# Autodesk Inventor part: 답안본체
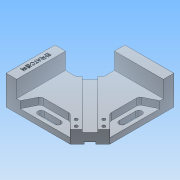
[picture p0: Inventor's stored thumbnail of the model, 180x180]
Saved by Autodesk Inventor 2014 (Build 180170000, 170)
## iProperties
Created: 2019-04
Part Number: 답안본체
Material: 알루미늄 6061
Document SubType Name: Modeling
Designer: net
Density: 2.71 g/cm^3
Appearance: 알루미늄 - 평지
Mass: 603.738 g
Surface Area: 426.536 cm^2
Volume: 222.782 cm^3
Author: net
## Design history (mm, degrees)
sketch "스케치1"
  geometry: L1 (-60, -60)-(60, -60); L2 (60, -60)-(60, 60); L3 (60, 60)-(-60, 60); L4 (-60, 60)-(-60, -60); L5 (-60, -60)-(60, 60); L6 (60, -60)-(-60, 60); 1 further point
  constraints: 12 end point, 2 midpoint, 2 parallel, 1 horizontal, 1 perpendicular
  dimensions: "d0" = 120 distance of L2.end L3.end; "d1" = 120 distance of L3.end L1.start
extrude "돌출1" new body sketch "스케치1" stored distance "d2" = 42; taper "d3" = 0 deg
sketch "스케치2"
  geometry: L1 (-60, -60)-(60, -60) reference; L2 (60, -60)-(60, 60) reference; L3 (31.716, -60)-(60, -31.716); 1 further point
  constraints: 2 end point, 2 point on line
  dimensions: "d7" = 20 distance from line of L1.end L3
extrude "돌출2" cut sketch "스케치2" distance "d8" = 42; taper "d9" = 0 deg
sketch "스케치3"
  geometry: L1 (31.716, -60)-(60, -31.716) reference; L2 (60, 60)-(-60, 60) reference; L3 (-60, 60)-(-60, -60) reference; L4 (-60, 10)-(-10, 10); L5 (-10, 10)-(-10, 60); L6 (-10, 29.806)-(-29.806, 10); 1 further point
  constraints: 6 end point, 4 point on line, 2 perpendicular, 1 parallel
  dimensions: "d10" = 50 distance of L4.end L5.end; "d11" = 50 distance of L4.start L4.end; "d12" = 93 distance between parallel lines of L1 L6
extrude "돌출3" cut sketch "스케치3" distance "d13" = 42; taper "d14" = 0 deg
sketch "스케치4"
  geometry: L1 (-10, 60)-(-10, 29.806) reference; L2 (-10, 29.806)-(-29.806, 10) reference; L3 (-29.806, 10)-(-60, 10) reference; L4 (-60, 10)-(-60, -60) reference; L5 (-60, -60)-(31.716, -60) reference; L6 (31.716, -60)-(60, -31.716) reference; L7 (60, -31.716)-(60, 60) reference; L8 (60, 60)-(-10, 60) reference; L9 (-45, 10)-(-45, -60); L10 (-10, 45)-(60, 45); 1 further point
  constraints: 4 end point, 4 point on line, 2 perpendicular
  dimensions: "d15" = 15 distance between parallel lines of L4 L9; "d16" = 15 distance between parallel lines of L8 L10
extrude "돌출4" cut sketch "스케치4" distance "d17" = 24; taper "d18" = 0 deg
sketch "스케치5"
  geometry: L1 (-29.806, 10)-(-10, 29.806) reference; L2 (31.716, -60)-(-45, -60) reference; L3 (60, -31.716)-(31.716, -60) reference; L4 (-10, 29.806)-(-10, 45) reference; L5 (-40, -60)-(-30, -40); L6 (-30, -40)-(11.716, -40); L7 (11.716, -40)-(31.716, -60); L8 (-60, 10)-(-60, -60) reference; L9 (-19.903, 19.903)-(45.858, -45.858); 1 further point
  constraints: 8 end point, 2 midpoint, 2 point on line, 1 parallel, 1 perpendicular
  dimensions: "d19" = 20 distance from line of L5.start L8; "d20" = 30 horizontal distance of L8.end L5.end; "d21" = 20 distance between parallel lines of L9 L7; "d22" = 20 distance between parallel lines of L2 L6
extrude "돌출5" cut sketch "스케치5" distance "d23" = 10; taper "d24" = 0 deg
sketch "스케치6"
  geometry: L1 (60, -31.716)-(31.716, -60) reference; L2 (60, 45)-(60, -31.716) reference; L3 (-29.806, 10)-(-10, 29.806) reference; L4 (-30, -40)-(11.716, -40) reference; L5 (60, 40)-(40, 30); L6 (40, 30)-(40, -11.716); L7 (40, -11.716)-(60, -31.716); L8 (-19.903, 19.903)-(45.858, -45.858); L9 (60, 60)-(-10, 60) reference; 1 further point
  constraints: 8 end point, 2 midpoint, 2 perpendicular, 1 parallel, 1 point on line
  dimensions: "d25" = 20 distance from line of L9 L5.start; "d26" = 30 distance from line of L9 L5.end; "d27" = 20 distance between parallel lines of L2 L6
extrude "돌출6" cut sketch "스케치6" distance "d28" = 10; taper "d29" = 0 deg
fillet "모깎기1" dims "d30" = 5
sketch "스케치7"
  geometry: L1 (-26.91, -40)-(9.645, -40) reference; L2 (31.716, -60)-(-40, -60) reference; L3 (-20, -50)-(4, -50); L4 (-20, -54.5)-(4, -54.5); L5 (4, -45.5)-(-20, -45.5); L6 (-60, 10)-(-60, -60) reference; A1 r 4.5 centre (-20, -50) between (-20, -45.5) and (-20, -54.5); A2 r 4.5 centre (4, -50) between (4, -54.5) and (4, -45.5); 2 further points
  constraints: 8 end point, 4 point on circle, 4 tangent, 2 centre point, 2 parallel, 1 midpoint
  dimensions: "d31" = 10 distance from line of L2 point (-8, -50); "d32" = 9 distance between parallel lines of L4 L5; "d33" = 40 distance from line of L6 L3.start; "d34" = 24 distance of L4.start L4.end
extrude "돌출7" cut sketch "스케치7" distance "d35" = 10; taper "d36" = 0 deg
sketch "스케치8"
  geometry: L1 (60, 40)-(60, -31.716) reference; L2 (40, -9.645)-(40, 26.91) reference; L3 (50, 20)-(50, -4); L4 (45.5, 20)-(45.5, -4); L5 (54.5, -4)-(54.5, 20); L6 (60, 60)-(-10, 60) reference; A1 r 4.5 centre (50, 20) between (54.5, 20) and (45.5, 20); A2 r 4.5 centre (50, -4) between (45.5, -4) and (54.5, -4); 2 further points
  constraints: 8 end point, 4 point on circle, 4 tangent, 2 centre point, 2 parallel, 1 midpoint
  dimensions: "d37" = 9 distance between parallel lines of L5 L4; "d38" = 10 distance from line of L1 point (50, 8); "d39" = 24 distance of L4.start L4.end; "d40" = 40 distance from line of L6 L3.start
extrude "돌출8" cut sketch "스케치8" distance "d41" = 10; taper "d42" = 0 deg
sketch "스케치9"
  geometry: L1 (-40, 0)-(0, 0) reference; L2 (-40, 18)-(0, 18) reference; L3 (-14, 15)-(-26, 15); L4 (-26, 15)-(-26, 18); L5 (-26, 18)-(-14, 18); L6 (-14, 18)-(-14, 15); L7 (-14, 15)-(-26, 18); L8 (-26, 15)-(-14, 18); L9 (-12, 3.5)-(-28, 3.5); L10 (-28, 3.5)-(-28, 0); L11 (-28, 0)-(-12, 0); L12 (-12, 0)-(-12, 3.5); L13 (-12, 3.5)-(-28, 0); L14 (-28, 3.5)-(-12, 0); 5 further points
  constraints: 24 end point, 6 midpoint, 4 parallel, 2 horizontal, 2 perpendicular, 2 point on line, 2 vertical alignment
  dimensions: "d43" = 16 distance of L9.start L9.end; "d44" = 3.5 distance of L11.end L9.start; "d45" = 12 distance of L3.start L3.end; "d46" = 3 distance of L3.end L4.end
extrude "돌출9" cut sketch "스케치9" stored distance "d47" = 10; taper "d48" = 0 deg
sketch "스케치10"
  geometry: L1 (40.201, -51.515)-(-25.56, 14.246) reference; L2 (40.201, -51.515)-(31.716, -60) reference; L3 (9.645, -40)-(-26.91, -40) reference; L4 (-31.382, -42.764)-(-40, -60) reference; L5 (-40, -60)-(-45, -60) reference; L6 (-45, -60)-(-60, -60) reference; L7 (-60, -60)-(-60, 10) reference; L8 (-60, 10)-(-45, 10) reference; L9 (-45, 10)-(-29.806, 10) reference; L10 (-29.806, 10)-(-25.56, 14.246) reference; L11 (-25.56, 14.246)-(40.201, -51.515) reference; L12 (40.201, -51.515)-(31.716, -60) reference; L13 (31.716, -60)-(13.18, -41.464) reference; L14 (-45, 10)-(-45, -60) reference; L15 (60, 45)-(-10, 45) reference; L16 (-10, 29.806)-(-10, 45) reference; L17 (-14.246, 25.56)-(-10, 29.806) reference; L18 (51.515, -40.201)-(-14.246, 25.56) reference; L19 (60, -31.716)-(51.515, -40.201) reference; L20 (41.464, -13.18)-(60, -31.716) reference; L21 (40, 26.91)-(40, -9.645) reference; L22 (60, 40)-(42.764, 31.382) reference; L23 (60, 45)-(60, 40) reference; L24 (60, 60)-(60, 45) reference; L25 (-10, 60)-(60, 60) reference; L26 (-10, 45)-(-10, 60) reference; L27 (9.645, -40)-(-26.91, -40) reference; L28 (-31.382, -42.764)-(-40, -60) reference; L29 (-40, -60)-(-45, -60) reference; L30 (-45, -60)-(-60, -60) reference; L31 (-60, -60)-(-60, 10) reference; L32 (-60, 10)-(-45, 10) reference; L33 (-45, 10)-(-29.806, 10) reference; L34 (-29.806, 10)-(-25.56, 14.246) reference; L35 (-25.56, 14.246)-(40.201, -51.515) reference; L36 (40.201, -51.515)-(31.716, -60) reference; L37 (31.716, -60)-(13.18, -41.464) reference; L38 (-45, 10)-(-45, -60) reference; L39 (60, 45)-(-10, 45) reference; L40 (-10, 29.806)-(-10, 45) reference; L41 (-14.246, 25.56)-(-10, 29.806) reference; L42 (51.515, -40.201)-(-14.246, 25.56) reference; L43 (60, -31.716)-(51.515, -40.201) reference; L44 (41.464, -13.18)-(60, -31.716) reference; L45 (40, 26.91)-(40, -9.645) reference; L46 (60, 40)-(42.764, 31.382) reference; L47 (60, 45)-(60, 40) reference; L48 (60, 60)-(60, 45) reference; L49 (-10, 60)-(60, 60) reference; L50 (-10, 45)-(-10, 60) reference; C1 r 2.25 at (31.716, -51.515); C2 r 2.25 at (23.23, -43.029); C3 r 2.25 at (43.029, -23.23); C4 r 2.25 at (51.515, -31.716); A1 r 5 centre (9.645, -45) between (13.18, -41.464) and (9.645, -40) reference; A2 r 5 centre (-26.91, -45) between (-26.91, -40) and (-31.382, -42.764) reference; A3 r 5 centre (45, -9.645) between (40, -9.645) and (41.464, -13.18) reference; A4 r 5 centre (45, 26.91) between (42.764, 31.382) and (40, 26.91) reference; A5 r 5 centre (9.645, -45) between (13.18, -41.464) and (9.645, -40) reference; A6 r 5 centre (-26.91, -45) between (-26.91, -40) and (-31.382, -42.764) reference; A7 r 5 centre (45, -9.645) between (40, -9.645) and (41.464, -13.18) reference; A8 r 5 centre (45, 26.91) between (42.764, 31.382) and (40, 26.91) reference; 1 further point
  constraints: 4 centre point
  dimensions: "d49" = 4.5 diameter of C1; "d50" = 4.5 diameter of C2; "d51" = 4.5 diameter of C3; "d52" = 4.5 diameter of C4; "d53" = 6 distance from line of L2 C1.centre; "d54" = 6 distance from line of L1 C1.centre; "d55" = 6 distance from line of L43 C4.centre; "d56" = 6 distance from line of L42 C4.centre; "d57" = 18 distance from line of L2 C2.centre; "d58" = 18 distance from line of L19 C3.centre; "d59" = 6 distance from line of L20 C3.centre; "d60" = 6 distance from line of L1 C2.centre
extrude "돌출10" cut sketch "스케치10" stored distance "d61" = 10; taper "d62" = 0 deg
sketch "스케치11"
  geometry: L1 (15.66, 24.146)-(-50.101, -41.615) reference; L2 (-50.101, -41.615)-(-60, -31.716) reference; L3 (-60, -31.716)-(-60, 60) reference; L4 (-60, 60)-(10, 60) reference; L5 (10, 60)-(10, 29.806) reference; L6 (10, 29.806)-(15.66, 24.146) reference; L7 (-54.5, 20)-(-54.5, -4) reference; L8 (-45.5, -4)-(-45.5, 20) reference; L9 (20, -45.5)-(-4, -45.5) reference; L10 (-4, -54.5)-(20, -54.5) reference; L11 (60, -60)-(-31.716, -60) reference; L12 (-31.716, -60)-(-41.615, -50.101) reference; L13 (-41.615, -50.101)-(24.146, 15.66) reference; L14 (24.146, 15.66)-(29.806, 10) reference; L15 (29.806, 10)-(60, 10) reference; L16 (60, 10)-(60, -60) reference; C1 r 2.25 at (-31.716, -51.515) reference; C2 r 2.25 at (-23.23, -43.029) reference; C3 r 2.25 at (-31.716, -51.515) reference; C4 r 2.25 at (-43.029, -23.23) reference; C5 r 2.25 at (-51.515, -31.716) reference; C6 r 2.25 at (-23.23, -43.029) reference; C7 r 4 at (-43.029, -23.23); C8 r 4 at (-51.515, -31.716); C9 r 4 at (-23.23, -43.029); C10 r 4 at (-31.716, -51.515); A1 r 4.5 centre (-50, 20) between (-45.5, 20) and (-54.5, 20) reference; A2 r 4.5 centre (-50, -4) between (-54.5, -4) and (-45.5, -4) reference; A3 r 4.5 centre (20, -50) between (20, -54.5) and (20, -45.5) reference; A4 r 4.5 centre (-4, -50) between (-4, -45.5) and (-4, -54.5) reference; 1 further point
  constraints: 4 centre point, 4 coincident
  dimensions: "d63" = 8 diameter of C7; "d64" = 8 diameter of C8; "d65" = 8 diameter of C9; "d66" = 8 diameter of C10
extrude "돌출11" cut sketch "스케치11" distance "d67" = 10; taper "d68" = 0 deg
fillet "모깎기2" dims "d69" = 5
sketch "스케치12"
  geometry: L1 (-60, 10)-(-60, -60) reference; 3 further points
  constraints: 1 other
  dimensions: "d70" = 7.5 distance from line of L1 point (-52.5, -25); "d71" = 35 vertical distance of point (-45, 10) point (-52.5, -25)
feature "엠보싱1" sketch "스케치12" dims "d0" = 120, "d1" = 120, "d10" = 50, "d11" = 50, "d12" = 93, "d72" = 0.5, "d73" = 0
node "솔리드1"
node "절단 모서리 투영1"
node "절단 모서리 투영2"
node "절단 모서리 투영3"
